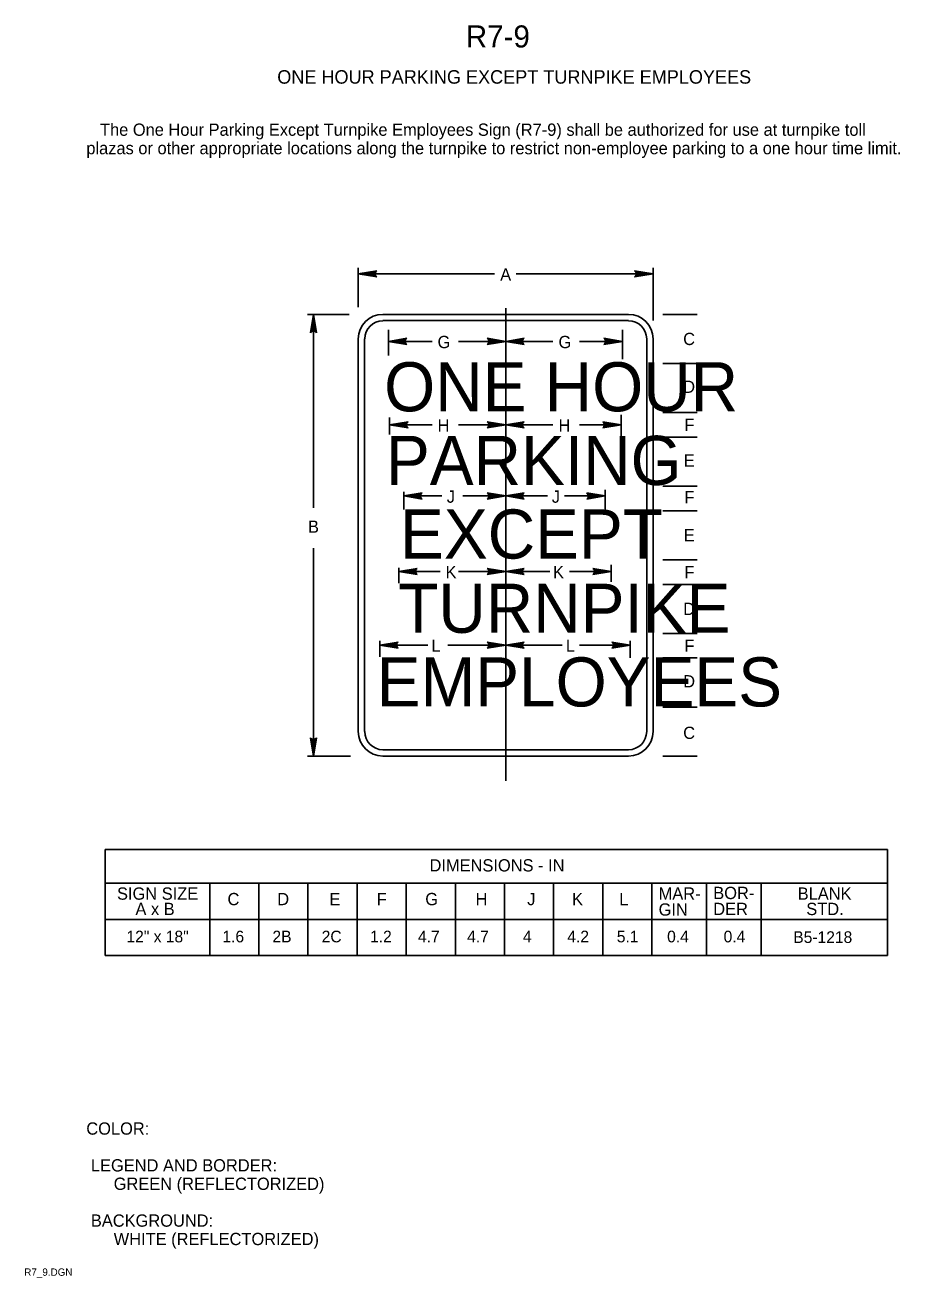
# Model space of a CAD drawing. Extents: x 0.013 to 0.191, y 0.004 to 0.259.
import ezdxf

# ---------------------------------------------------------------- set-up
doc = ezdxf.new("R2010")
doc.units = 0
for name, color, linetype in [('1', 7, 'Continuous'), ('11', 7, 'Continuous'), ('12', 7, 'Continuous'), ('2', 7, 'Continuous'), ('3', 7, 'Continuous')]:
    doc.layers.add(name, color=color, linetype=linetype)

# ---------------------------------------------------------------- blocks, each defined once
blk = doc.blocks.new('RARROW')
at = {"layer": '3'}
for p, q in [((-2.156, 0.285), (-2.2665, 0.384625)), ((-2.2665, 0.384625), (0, 0)), ((0, 0), (-2.2665, -0.379125)), ((-2.156, 0.285), (-2.075625, 0.12075)), ((0, 0), (-2.156, 0.285)), ((-2.14975, -0.2705), (0, 0)), ((-2.075625, 0.12075), (0, 0)), ((0, 0), (-2.074, -0.108)), ((-2.2665, -0.379125), (-2.14975, -0.2705)), ((-2.074, -0.108), (-2.14975, -0.2705))]:
    blk.add_line(p, q, dxfattribs=at)

msp = doc.modelspace()

# ---------------------------------------------------------------- linework, layer by layer
at = {"layer": '1'}
for p, q in [((0.1105, 0.2015), (0.1105, 0.10525)), ((0.08688, 0.17925), (0.08688, 0.17575)), ((0.134, 0.17975), (0.134, 0.17538)), ((0.08975, 0.16412), (0.08975, 0.1605)), ((0.13075, 0.1645), (0.13075, 0.1605)), ((0.08875, 0.14863), (0.08875, 0.1455)), ((0.132, 0.14925), (0.132, 0.14575)), ((0.08488, 0.13375), (0.08488, 0.1305)), ((0.13587, 0.13375), (0.13587, 0.13025))]:
    msp.add_line(p, q, dxfattribs=at)
at = {"layer": '11'}
for p, q in [((0.0855, 0.20025), (0.1355, 0.20025)), ((0.0805, 0.11525), (0.0805, 0.19525)), ((0.1405, 0.19525), (0.1405, 0.11525)), ((0.1355, 0.11025), (0.0855, 0.11025))]:
    msp.add_line(p, q, dxfattribs=at)
for centre, start, end in [((0.0855, 0.19525), 90, 180), ((0.1355, 0.19525), 0, 90), ((0.0855, 0.11525), 180, 270), ((0.1355, 0.11525), 270, 0)]:
    msp.add_arc(centre, 0.005, start, end, dxfattribs=at)
at = {"layer": '3'}
for p, q in [((0.0805, 0.20175), (0.0805, 0.20975)), ((0.1405, 0.199), (0.1405, 0.20975)), ((0.10825, 0.2085), (0.0805, 0.2085)), ((0.11263, 0.2085), (0.1405, 0.2085)), ((0.07863, 0.20025), (0.07013, 0.20025)), ((0.07138, 0.16087), (0.07138, 0.20025)), ((0.1425, 0.20025), (0.1495, 0.20025)), ((0.0855, 0.199), (0.1355, 0.199)), ((0.08663, 0.19188), (0.08663, 0.19712)), ((0.1105, 0.19662), (0.1105, 0.1935)), ((0.13425, 0.19113), (0.13425, 0.19712)), ((0.08175, 0.11525), (0.08175, 0.19525)), ((0.0955, 0.19475), (0.08663, 0.19475)), ((0.10088, 0.19475), (0.1105, 0.19475)), ((0.12012, 0.19475), (0.1105, 0.19475)), ((0.1255, 0.19475), (0.13425, 0.19475)), ((0.13925, 0.19525), (0.13925, 0.11525)), ((0.1425, 0.19025), (0.1495, 0.19025)), ((0.1105, 0.17963), (0.1105, 0.1765)), ((0.1425, 0.18025), (0.1495, 0.18025)), ((0.0955, 0.17775), (0.08688, 0.17775)), ((0.10088, 0.17775), (0.1105, 0.17775)), ((0.12012, 0.17775), (0.1105, 0.17775)), ((0.1255, 0.17775), (0.134, 0.17775)), ((0.1425, 0.17525), (0.1495, 0.17525)), ((0.1105, 0.16512), (0.1105, 0.162)), ((0.1425, 0.16525), (0.1495, 0.16525)), ((0.0975, 0.16325), (0.08975, 0.16325)), ((0.10175, 0.16325), (0.1105, 0.16325)), ((0.119, 0.16325), (0.1105, 0.16325)), ((0.1225, 0.16325), (0.13075, 0.16325)), ((0.1425, 0.16025), (0.1495, 0.16025)), ((0.07138, 0.15263), (0.07138, 0.11025)), ((0.1105, 0.14975), (0.1105, 0.14663)), ((0.1425, 0.15025), (0.1495, 0.15025)), ((0.09713, 0.14788), (0.08875, 0.14788)), ((0.10088, 0.14788), (0.1105, 0.14788)), ((0.1195, 0.14788), (0.1105, 0.14788)), ((0.1235, 0.14788), (0.132, 0.14788)), ((0.1425, 0.14525), (0.1495, 0.14525)), ((0.09463, 0.13287), (0.08488, 0.13287)), ((0.09875, 0.13287), (0.1105, 0.13287)), ((0.1105, 0.13475), (0.1105, 0.13162)), ((0.122, 0.13287), (0.1105, 0.13287)), ((0.1255, 0.13287), (0.13587, 0.13287)), ((0.1425, 0.13525), (0.1495, 0.13525)), ((0.1425, 0.13025), (0.1495, 0.13025)), ((0.1425, 0.12025), (0.1495, 0.12025)), ((0.07888, 0.11025), (0.07013, 0.11025)), ((0.1355, 0.1115), (0.0855, 0.1115)), ((0.1425, 0.11025), (0.1495, 0.11025)), ((0.029, 0.09125), (0.18825, 0.09125)), ((0.029, 0.09125), (0.029, 0.06963)), ((0.18825, 0.09125), (0.18825, 0.06963)), ((0.029, 0.08438), (0.18825, 0.08438)), ((0.05025, 0.08438), (0.05025, 0.06963)), ((0.06025, 0.08438), (0.06025, 0.06963)), ((0.07025, 0.08438), (0.07025, 0.06963)), ((0.08025, 0.08438), (0.08025, 0.06963)), ((0.09025, 0.08438), (0.09025, 0.06963)), ((0.10025, 0.08438), (0.10025, 0.06963)), ((0.11025, 0.08438), (0.11025, 0.06963)), ((0.12025, 0.08438), (0.12025, 0.06963)), ((0.13025, 0.08438), (0.13025, 0.06963)), ((0.14025, 0.08438), (0.14025, 0.06963)), ((0.15138, 0.08438), (0.15138, 0.06963)), ((0.1625, 0.08438), (0.1625, 0.06963)), ((0.029, 0.077), (0.18825, 0.077)), ((0.029, 0.06963), (0.18825, 0.06963))]:
    msp.add_line(p, q, dxfattribs=at)
for centre, start, end in [((0.0855, 0.19525), 90, 180), ((0.1355, 0.19525), 0, 90), ((0.0855, 0.11525), 180, 270), ((0.1355, 0.11525), 270, 0)]:
    msp.add_arc(centre, 0.0037, start, end, dxfattribs=at)

# ---------------------------------------------------------------- block references
at = {"layer": '3', "xscale": 0.0016545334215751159, "yscale": 0.0016366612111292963}
for p, rotation in [((0.0805, 0.2085), 180), ((0.07138, 0.20025), 90), ((0.08663, 0.19475), 180), ((0.1105, 0.19475), 180), ((0.08688, 0.17775), 180), ((0.1105, 0.17775), 180), ((0.08975, 0.16325), 180), ((0.1105, 0.16325), 180), ((0.08875, 0.14788), 180), ((0.1105, 0.14788), 180), ((0.08488, 0.13287), 180), ((0.1105, 0.13287), 180), ((0.07138, 0.11025), -90)]:
    msp.add_blockref('RARROW', p, dxfattribs=dict(at, rotation=rotation))
for p in [(0.1405, 0.2085), (0.1105, 0.19475), (0.13425, 0.19475), (0.1105, 0.17775), (0.134, 0.17775), (0.1105, 0.16325), (0.13075, 0.16325), (0.1105, 0.14788), (0.132, 0.14788), (0.1105, 0.13287), (0.13587, 0.13287)]:
    msp.add_blockref('RARROW', p, dxfattribs=at)

# ---------------------------------------------------------------- texts
at = {"layer": '1'}
for s, height, p in [('R7-9', 0.0045, (0.10238, 0.25462)), ('ONE HOUR PARKING EXCEPT TURNPIKE EMPLOYEES', 0.0027503, (0.064, 0.24725)), ('COLOR:', 0.0025, (0.02513, 0.03313)), (' LEGEND AND BORDER:', 0.0024998, (0.02513, 0.02563)), ('      GREEN (REFLECTORIZED)', 0.0024998, (0.02513, 0.02188)), (' BACKGROUND:', 0.0024998, (0.02513, 0.01438)), ('      WHITE (REFLECTORIZED)', 0.0024998, (0.02513, 0.01063)), ('R7_9.DGN', 0.0015, (0.0125, 0.00438))]:
    msp.add_text(s, height=height, dxfattribs=at).set_placement(p)
at = {"layer": '12'}
for s, p in [('ONE HOUR', (0.08575, 0.1805)), ('PARKING', (0.08613, 0.1655)), ('EXCEPT', (0.089, 0.1505)), ('TURNPIKE', (0.08862, 0.13537)), ('EMPLOYEES', (0.08425, 0.12037))]:
    msp.add_text(s, height=0.01, dxfattribs=at).set_placement(p)
at = {"layer": '2'}
for s, p in [('   The One Hour Parking Except Turnpike Employees Sign (R7-9) shall be authorized for use at turnpike toll', (0.02513, 0.23663)), ('plazas or other appropriate locations along the turnpike to restrict non-employee parking to a one hour time limit.', (0.02513, 0.23287))]:
    msp.add_text(s, height=0.00249975, dxfattribs=at).set_placement(p)
at = {"layer": '3'}
for s, height, p in [('A', 0.0025, (0.10938, 0.20713)), ('G ', 0.0025, (0.09663, 0.19337)), ('G ', 0.0025, (0.12125, 0.19337)), ('C', 0.0025, (0.14663, 0.194)), ('D', 0.0025, (0.14663, 0.18425)), ('H ', 0.0025, (0.09663, 0.17638)), ('H ', 0.0025, (0.12125, 0.17638)), ('F', 0.0025, (0.14688, 0.1765)), ('E', 0.0025, (0.14675, 0.16925)), ('J ', 0.0025, (0.0985, 0.16187)), ('J ', 0.0025, (0.11988, 0.16187)), ('F', 0.0025, (0.14688, 0.16175)), ('B', 0.0025, (0.07025, 0.15575)), ('E', 0.0025, (0.14675, 0.154)), ('K ', 0.0025, (0.09825, 0.1465)), ('K ', 0.0025, (0.12012, 0.1465)), ('F', 0.0025, (0.14688, 0.1465)), ('D', 0.0025, (0.14663, 0.139)), ('L ', 0.0025, (0.09538, 0.1315)), ('L ', 0.0025, (0.12275, 0.1315)), ('F', 0.0025, (0.14688, 0.1315)), ('D', 0.0025, (0.14663, 0.12425)), ('C', 0.0025, (0.14663, 0.11375)), ('DIMENSIONS - IN', 0.0024998, (0.09499, 0.08675)), ('SIGN SIZE', 0.0025, (0.03138, 0.081)), ('C', 0.0025, (0.05387, 0.07988)), ('D', 0.0025, (0.064, 0.07988)), ('E', 0.0025, (0.07462, 0.07988)), ('F', 0.0025, (0.08425, 0.07988)), ('G', 0.0025, (0.09413, 0.07988)), ('H', 0.0025, (0.10437, 0.07988)), ('J', 0.0025, (0.11488, 0.07988)), ('K', 0.0025, (0.124, 0.07988)), ('L', 0.0025, (0.13362, 0.07988)), ('MAR-', 0.0025, (0.14163, 0.081)), ('BOR-', 0.0025, (0.15275, 0.08113)), ('BLANK', 0.0025, (0.16994, 0.081)), ('A x B', 0.0025, (0.03513, 0.07787)), ('GIN', 0.0025, (0.14163, 0.07775)), ('DER', 0.0025, (0.15275, 0.07787)), ('STD.', 0.0025, (0.17169, 0.07787)), ('12" x 18"', 0.002375, (0.0333, 0.07231)), ('1.6', 0.002375, (0.05283, 0.07231)), ('2B', 0.002375, (0.06302, 0.07231)), ('2C', 0.002375, (0.07304, 0.07231)), ('1.2', 0.002375, (0.08289, 0.07231)), ('4.7', 0.002375, (0.09265, 0.07231)), ('4.7', 0.002375, (0.10265, 0.07231)), ('4', 0.00238, (0.11401, 0.07231)), ('4.2', 0.002375, (0.12304, 0.07231)), ('5.1', 0.002375, (0.13312, 0.07231)), ('0.4', 0.002375, (0.14336, 0.07231)), ('0.4', 0.002375, (0.15486, 0.07231)), ('B5-1218', 0.002375, (0.16904, 0.07219))]:
    msp.add_text(s, height=height, dxfattribs=at).set_placement(p)

doc.saveas('drawing.dxf')
